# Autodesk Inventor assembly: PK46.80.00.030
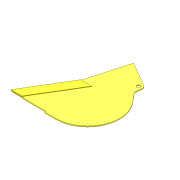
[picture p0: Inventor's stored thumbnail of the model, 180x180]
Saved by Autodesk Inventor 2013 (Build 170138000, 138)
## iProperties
Shininess: 64.0
Length Units: 11269
Angle Units: 11279
Time Units: 11290
Mass Units: 11283
Length Display Precision: 3
Angle Display Precision: 2
Compacted: True
Created: 2005-01
Part Number: PK46.80.00.030
Document SubType Name: Assembly
Designer: SAlex
Manufacturer: Standard
Standards Organization: Custom
Density: 0.0
Volumn: 0.0
Area: 0.0
PropertySet Name: Model Information
Control State: 0
Master: False
Checked Out: False
Checked Out Date: 2008-10-15
Last Check In Date: 2008-10-15
Author: SAlex
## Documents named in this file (3)
- C:\Product Design Suite 2013 Test Drive\Dynamic Simulation\Workspace\Assy, Chassis, Front\PK46.80.00.030.iam
- C:\Product Design Suite 2013 Test Drive\Dynamic Simulation\Workspace\Assy, Chassis, Front\PK46.80.00.017.ipt
- C:\Product Design Suite 2013 Test Drive\Dynamic Simulation\Workspace\Assy, Chassis, Front\PK46.80.00.019.ipt
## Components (2 placed, 2 different names)
1. PK46.80.00.017:1 — Совмещение:1, Заподлицо:1, Совмещение:2
2. PK46.80.00.019:1 — Совмещение:1, Заподлицо:1, Совмещение:2
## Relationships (3: Mate 2, Flush 1)
- Совмещение:1 [Mate]: PK46.80.00.017:1 ↔ PK46.80.00.019:1
- Заподлицо:1 [Flush]: PK46.80.00.017:1 ↔ PK46.80.00.019:1
- Совмещение:2 [Mate]: PK46.80.00.017:1 ↔ PK46.80.00.019:1
